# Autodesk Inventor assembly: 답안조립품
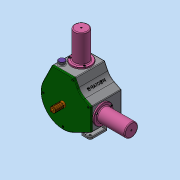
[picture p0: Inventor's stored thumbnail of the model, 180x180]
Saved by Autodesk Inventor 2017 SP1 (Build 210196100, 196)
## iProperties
Part Number: 답안조립품
Material: 일반
Document SubType Name: Assembly
Designer: MRC
Mass: 2899.53 g
Surface Area: 4101.75 cm^2
Volume: 1119.43 cm^3
Density: 2.59018 g/cm^3
Author: MRC
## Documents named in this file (13)
- C:\Users\MRC\Desktop\611109V1005\답안조립품.iam
- C:\Users\MRC\Desktop\611109V1005\본체.ipt
- C:\Users\MRC\Desktop\611109V1005\너트 M3.ipt
- C:\Users\MRC\Desktop\611109V1005\베어링 20 x 37 x 9.ipt
- C:\Users\MRC\Desktop\611109V1005\볼트 M3 x 12.ipt
- C:\Users\MRC\Desktop\611109V1005\실린더.ipt
- C:\Users\MRC\Desktop\611109V1005\앞커버.ipt
- C:\Users\MRC\Desktop\611109V1005\축.ipt
- C:\Users\MRC\Desktop\611109V1005\측정게이지.ipt
- C:\Users\MRC\Desktop\611109V1005\커넥팅로드 캡.ipt
- C:\Users\MRC\Desktop\611109V1005\커넥팅로드.ipt
- C:\Users\MRC\Desktop\611109V1005\피스톤 핀.ipt
- C:\Users\MRC\Desktop\611109V1005\피스톤.ipt
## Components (4 placed, 2 different names)
1. 피스톤 핀:1
2. 피스톤:1
3. 피스톤 핀:2 — 플러쉬:1
4. 피스톤:2 — 플러쉬:1
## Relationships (1: Flush 1)
- 플러쉬:1 [Flush]: 피스톤 핀:2 ↔ 피스톤:2
## Named parameters: d24_d22 = 0
